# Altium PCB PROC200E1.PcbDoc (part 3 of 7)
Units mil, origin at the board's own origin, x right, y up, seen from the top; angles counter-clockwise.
Board outline 4163.97 x 3505.34 mil, 6 copper layers (Top Layer, GND1, SIG1, PWR, GND2, Bottom), stack 58.132 mil thick; 367 components, 387 nets, 1784 pads, 858 vias.
Unrouted connection lines stored in the file: 17.
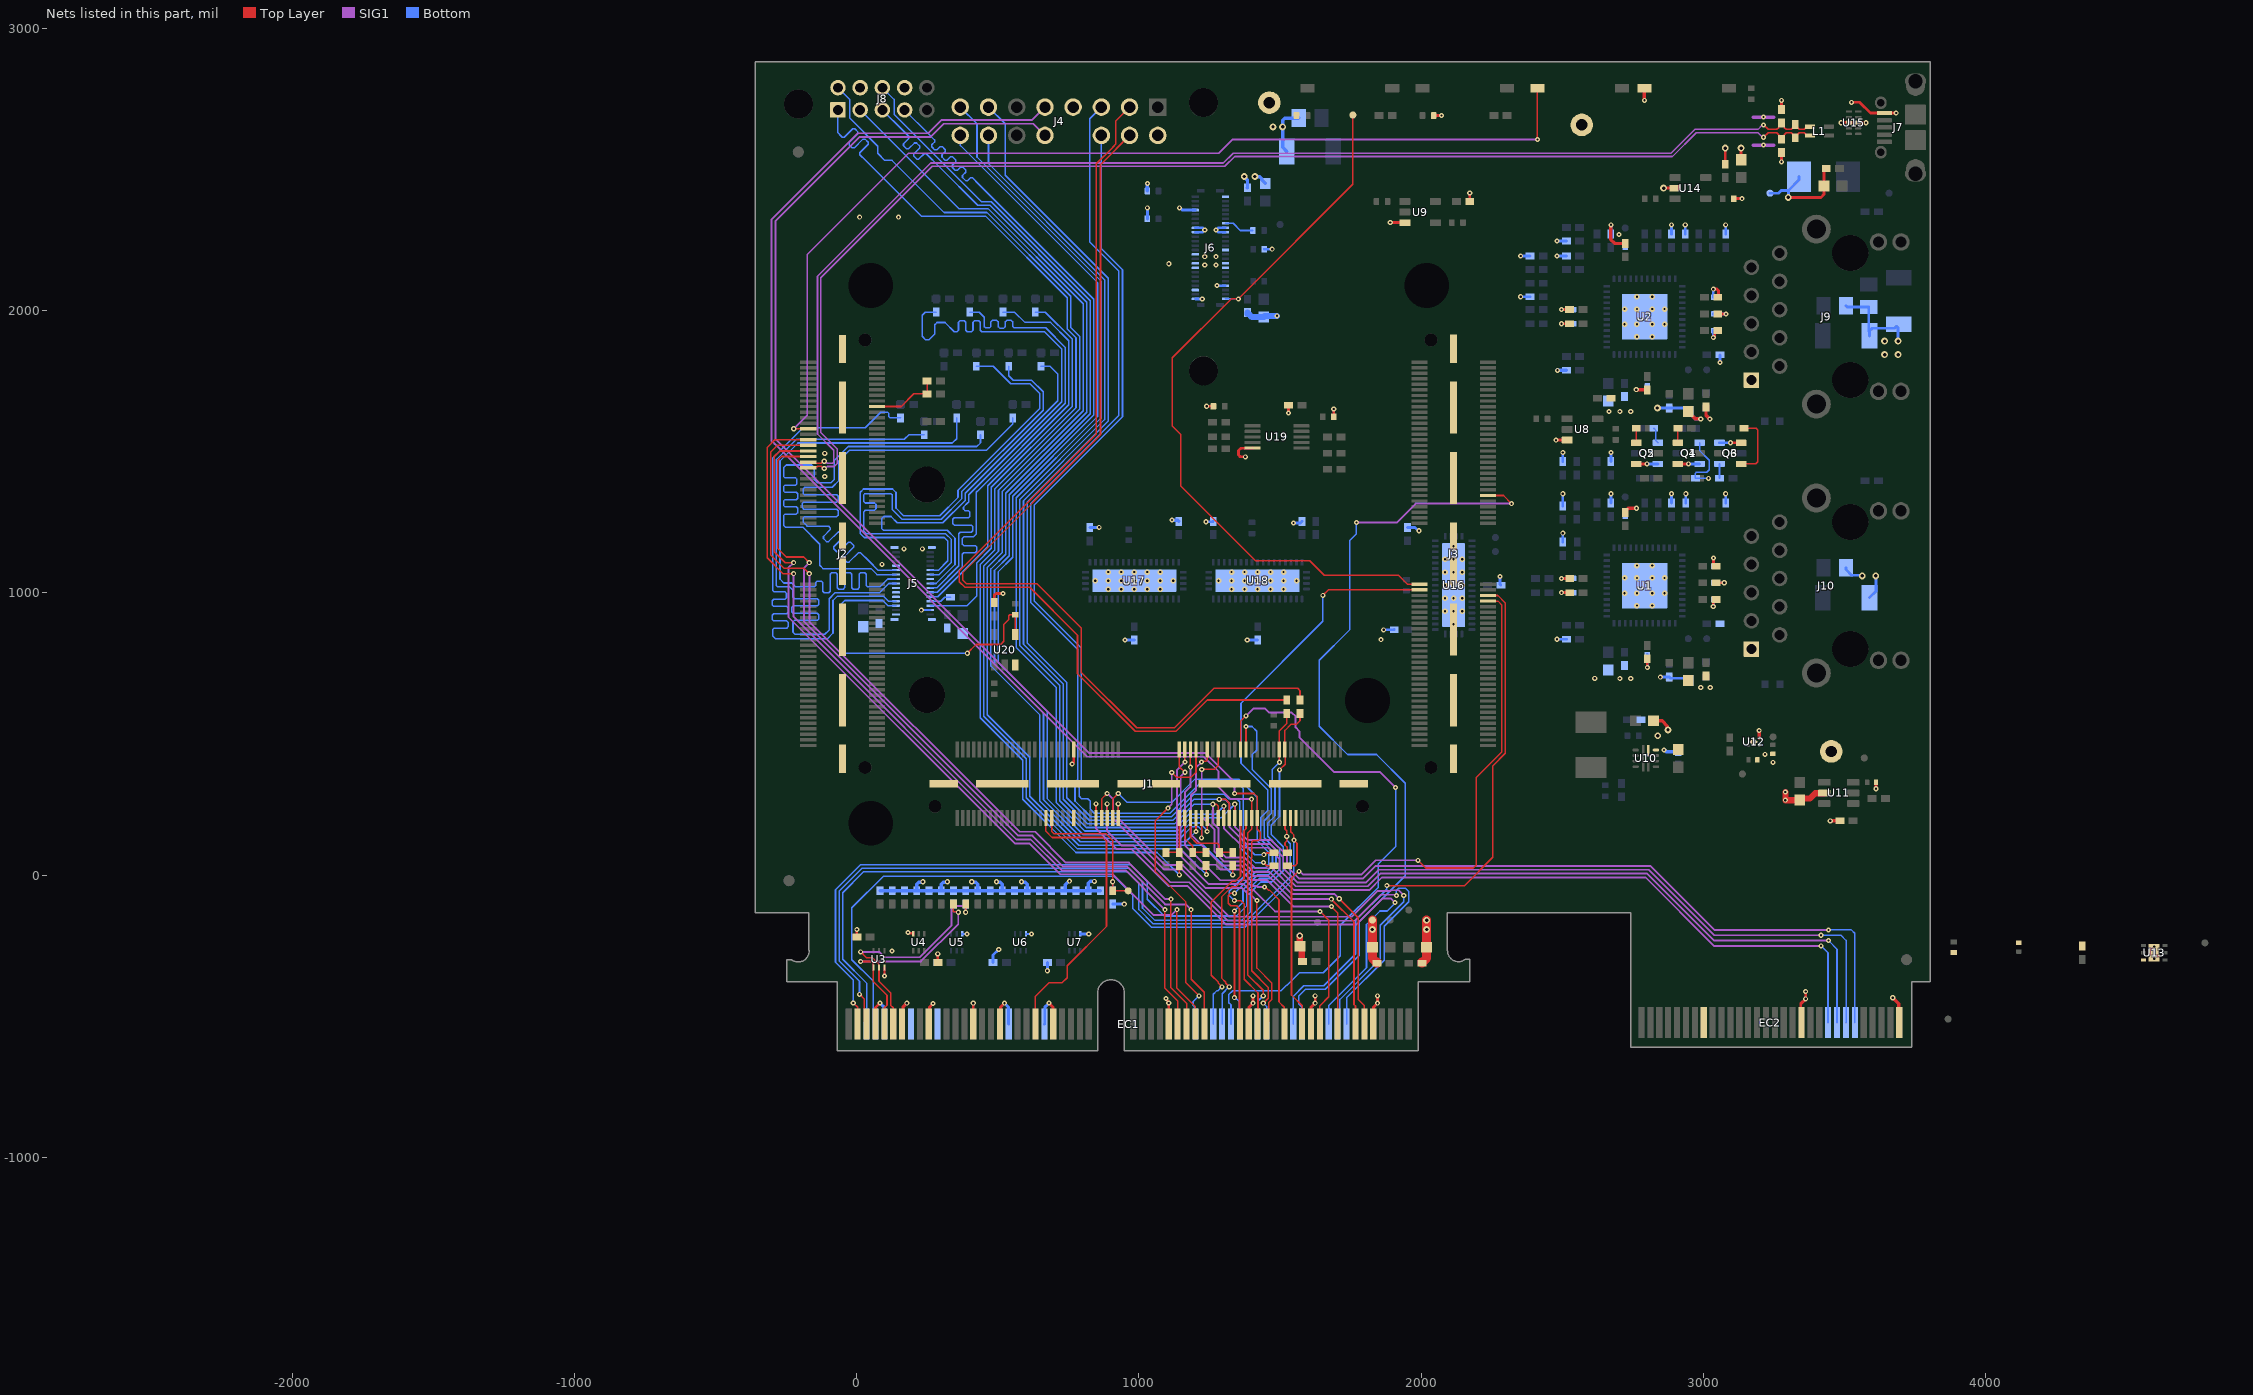
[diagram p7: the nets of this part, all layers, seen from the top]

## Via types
v1: diameter 18, hole 8, Top Layer to Bottom, tented both sides, 729 vias
v2: diameter 19.68, hole 7.87, Top Layer to Bottom, 77 vias
v3: diameter 24, hole 12, Top Layer to Bottom, tented both sides, 52 vias

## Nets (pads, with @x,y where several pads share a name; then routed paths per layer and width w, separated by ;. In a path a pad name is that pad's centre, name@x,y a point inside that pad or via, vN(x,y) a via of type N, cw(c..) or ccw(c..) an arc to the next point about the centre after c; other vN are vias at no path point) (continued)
AM26x_EQEP0_B: EC1.102 J1.69 | length 1926.2
  Top Layer w5.66: J1.69@847.97,201.89 v1(847.97,252.36)
  SIG1 w6.66: v1(847.97,252.36) 847.97,164.6 920.86,91.71 974.35,91.71 1105.1,-39.05 1172.37,-39.05 1308.99,-175.68 1770.43,-175.68 1862.69,-83.41 1893.44,-83.41 1907.51,-97.49 v1(1907.51,-97.56)
  Bottom w5.66: EC1.102@1672.7,-528.32 1672.7,-462.38 1806.39,-328.69 1806.39,-175.06 1854.07,-127.37 1880.23,-127.37 1907.51,-100.09 v1(1907.51,-97.56)
AM26x_EQEP0_INDEX: EC1.106 J1.65 | length 1973.5
  Top Layer w5.66: J1.65@887.34,201.89 v1(887.34,252.36)
  SIG1 w6.66: v1(887.34,252.36) 887.34,156.02 938,105.37 980.01,105.37 1110.76,-25.39 1178.02,-25.39 1314.65,-162.02 1764.77,-162.02 1857.03,-69.75 1899.1,-69.75 1899.18,-69.84 1910.14,-69.84 v1(1912.31,-72.01)
  Bottom w5.66: EC1.106@1735.69,-528.32 1735.69,-435.19 1869.38,-301.5 1869.38,-181.3 1956.3,-94.38 1956.3,-57.87 1945.86,-47.43 1919.06,-47.43 1912.31,-54.17 v1(1912.31,-72.01)
AM26x_EQEP0_STROBE: EC1.104 J1.67 | length 1967.2
  Top Layer w5.66: J1.67@867.66,201.89 867.66,269.68 v1(887.34,289.36)
  SIG1 w6.66: v1(887.34,289.36) 908.38,268.32 908.38,200.3 1089.5,19.19 1152.77,19.19 1319.53,-147.58 1754.04,-147.58 1845.53,-56.09 1891.39,-56.09 1893.8,-53.68 1919.98,-53.68 v1(1938.31,-72.01)
  Bottom w5.66: EC1.104@1704.2,-528.32 1712.19,-520.33 1712.19,-440.79 1855.38,-297.6 1855.38,-177.4 1938.31,-94.47 v1(1938.31,-72.01)
AM26x_FSIRX0_CLK: J1.55 R39.2 R40.2 | length 254
  Top Layer w5.66: J1.55@1182.62,201.89 1182.62,134.8 1204.46,112.96 1277.44,112.96 1285.23,105.17 R40.2@1285.23,80.5 R39.2@1332.54,80.5
AM26x_FSIRX0_DATA0: J1.59 R126.2 R127.2 | length 168.8
  Top Layer w5.66: R127.2@1096,80.5 R126.2@1143.25,80.5 ; J1.59@1143.25,201.89 R126.2@1143.25,80.55 ; R126.2@1143.25,80.5 R126.2@1143.25,80.55 ; R126.2@1143.25,80.5 R126.2@1143.31,80.5 R126.2@1143.25,80.55
AM26x_FSIRX0_DATA1: J1.57 R41.2 R125.2 | length 180.2
  Top Layer w5.66: J1.57@1162.93,201.89 1162.93,129.29 1190.61,101.61 R125.2@1190.61,80.5 R41.2@1237.92,80.5
AM26x_FSITX0_CLK: J1.49 J8.7 | length 3792.8
  Top Layer w5.66: v1(1241.67,154) J1.49@1241.67,201.89
  Bottom w5.66: J8.7@169.74,2711 255.8,2624.94 275.94,2604.8 275.94,2597.54 265.85,2587.45 265.85,2580.19 276.74,2569.31 284,2569.31 295.93,2581.24 303.19,2581.24 314.08,2570.36 314.08,2563.1 302.14,2551.16 302.14,2543.9 313.03,2533.02 320.29,2533.02 332.22,2544.95 339.48,2544.95 350.37,2534.07 350.37,2526.81 338.43,2514.87 338.43,2507.62 349.32,2496.73 356.57,2496.73 368.51,2508.66 375.77,2508.66 386.65,2497.78 386.65,2490.52 374.99,2478.85 374.99,2471.6 385.87,2460.71 393.13,2460.71 402.95,2470.53 410.21,2470.53 432.75,2447.99 840.4,2040.34 840.4,1629.73 553.06,1342.39 553.06,1126.09 500.92,1073.95 500.92,752.84 674.59,579.17 674.59,271.64 802.93,143.3 1141.52,143.3 1182.71,184.49 1214.93,184.49 1239.31,160.11 1239.31,156.36 v1(1241.67,154)
AM26x_FSITX0_DATA0: J1.53 J8.5 | length 3792.3
  Top Layer w5.66: v1(1202.3,154) J1.53@1202.3,201.89
  Bottom w5.66: J8.5@91,2711 164.5,2637.5 184.65,2617.35 184.65,2610.1 165.66,2591.11 165.66,2583.85 176.55,2572.97 183.81,2572.97 204.78,2593.94 212.03,2593.94 222.92,2583.05 222.92,2575.79 202.08,2554.96 202.08,2547.7 212.97,2536.81 220.23,2536.81 239.08,2555.66 246.34,2555.66 293,2509 429.02,2372.98 471.95,2372.98 815.08,2029.85 815.08,1640.22 527.74,1352.88 527.74,1136.58 475.6,1084.43 475.6,740.68 649.27,567.01 649.27,261.16 792.44,117.98 1166.28,117.98 v1(1202.3,154)
AM26x_FSITX0_DATA1: J1.51 J8.6 | length 3797.3
  Top Layer w5.66: v1(1221.99,132) J1.51@1221.99,201.89
  Bottom w5.66: J8.6@91,2789.74 132.55,2748.19 132.55,2695.59 442.5,2385.64 477.2,2385.64 827.74,2035.1 827.74,1634.98 540.4,1347.63 540.4,1131.33 488.26,1079.19 488.26,747.59 661.93,573.92 661.93,266.4 797.69,130.64 1146.76,130.64 1187.95,171.83 1209.69,171.83 1221.99,159.53 v1(1221.99,132)
AM26x_GPIO15: EC1.81 J3.57 | length 2180.3
  Top Layer w5.66: v1(1338.28,-64.45) 1324.8,-64.45 1316.31,-72.94 1316.31,-99.67 1325.7,-109.06 1346.32,-109.06 1356.34,-119.08 1356.34,-526.93 EC1.81@1357.74,-528.32 ; v1(1651.73,991) 1670.97,1010.24 J3.57@1993.48,1010.24
  Bottom w5.66: v1(1338.28,-64.45) 1416.03,13.3 1453.8,13.3 1473.09,32.6 1473.09,85.08 1431.5,126.68 1431.5,203.88 1456.54,228.92 1456.54,301.33 1361.64,396.24 1361.64,609.22 1651.73,899.31 v1(1651.73,991)
AM26x_GPIO81: EC1.96 J3.72 | length 2894.4
  Top Layer w5.66: J3.72@2236.48,1344.88 2291.59,1344.88 v1(2320.41,1316.07)
  SIG1 w6.66: v1(1770.7,1248.95) 1913.05,1248.95 1980.18,1316.07 v1@2321,1316.07
  Bottom w5.66: EC1.96@1578.21,-528.32 1577.81,-527.92 1577.81,-468.03 1566.27,-456.49 1566.27,-428.74 1590.16,-404.85 1660.15,-404.85 1781.07,-283.93 1781.07,-164.57 1943.57,-2.07 1943.57,325.34 1841.82,427.09 1739.25,427.09 1638.79,527.55 1638.79,761.04 1746.32,868.57 1746.32,1184.77 1770.7,1209.15 v1(1770.7,1248.95)
AM26x_I2C2_SCL: EC1.87 J1.61 | length 1181.2
  Top Layer w5.66: J1.61@926.71,201.89 v1(926.71,252.36) ; v1(1418.02,-90.45) 1418.02,-329.22 1470.85,-382.06 1470.85,-441.3 1460.22,-451.93 1460.22,-520.33 EC1.87@1452.23,-528.32
  SIG1 w6.66: v1(926.71,252.36) 926.71,201.29 1092.7,35.3 1155.97,35.3 1237.39,-46.12 1366.19,-46.12 1387.27,-67.2 1394.77,-67.2 v1(1418.02,-90.45)
AM26x_I2C2_SDA: EC1.85 J1.63 | length 1622.6
  Top Layer w5.66: J1.63@907.03,201.89 907.03,269.68 v1(926.71,289.36) ; v1(1338.12,-90.45) 1360.63,-90.45 1372.76,-102.58 1372.76,-368.85 1421.93,-418.02 1421.93,-527.13 EC1.85@1420.73,-528.32
  Bottom w5.66: v1(926.71,289.36) 957.91,258.17 1116.84,258.17 1198.77,340.1 1354.37,340.1 1418.84,275.63 1418.84,121.43 1446.47,93.8 1446.47,93.67 1460.43,79.71 1460.43,37.84 1448.56,25.96 1403.47,25.96 1320.45,-57.07 1320.45,-72.78 v1(1338.12,-90.45)
AM26x_LIN1_RXD: EC1.76 J1.37 | length 810.9
  Top Layer w5.66: v1(1293.91,-396.11) 1293.91,-395.79 1281.7,-383.58 1281.7,-379.58 1256.64,-354.52 1256.64,-95.18 1329.58,-22.24 1342.1,-22.24 1359.78,-4.56 J1.37@1359.78,201.89
  Bottom w5.66: EC1.76@1263.25,-528.32 1263.25,-422.44 1275.23,-410.46 1279.56,-410.46 v1(1293.91,-396.11)
AM26x_LIN1_TXD: EC1.78 J1.35 | length 797.6
  Top Layer w5.66: v1(1320.01,-396.11) 1320.01,-395.79 1307.81,-383.58 1307.81,-379.58 1292.82,-364.59 1292.82,-77.48 1328.29,-42 1344.02,-42 1372.44,-13.57 1372.44,156.89 1379.47,163.92 J1.35@1379.47,201.89
  Bottom w5.66: EC1.78@1294.75,-528.32 1294.75,-420.49 1319.12,-396.11 v1(1320.01,-396.11)
AM26x_MCAN0_RX: EC1.80 J1.38 | length 2056
  Top Layer w5.66: J1.38@1359.78,444.88 1360.14,445.24 1360.14,544.74 v1(1379.47,564.07)
  SIG1 w6.66: v1(1379.47,564.07) 1405.32,589.92 1446.92,589.92 1461.17,575.67 1541.31,575.67 1554.97,562.01 1554.97,523.03 1568.85,509.15 1568.85,487.71 1691.57,365 1854.45,365 v1(1909.29,310.15)
  Bottom w5.66: EC1.80@1326.24,-528.32 1326.24,-459.67 1318.64,-452.07 1318.64,-423.45 1332.54,-409.56 1503.62,-409.56 1522.24,-390.94 1523.67,-390.94 1568.57,-346.05 1653.05,-346.05 1713.66,-285.43 1713.66,-178.26 1847.27,-44.65 1847.27,38 1909.29,100.02 v1(1909.29,310.15)
AM26x_MCAN0_TX: EC1.82 J1.36 | length 1320.1
  Top Layer w5.66: v1(1338.12,-434.33) 1338.54,-433.91 v1@1338.54,-127.37 ; J1.36@1379.47,444.88 v1(1379.47,526.36)
  Bottom w5.66: v1(1338.12,-434.33) 1341.46,-434.33 1355.95,-448.83 1355.95,-526.54 EC1.82@1357.74,-528.32 ; v1(1338.12,-127.37) 1368.69,-96.8 1368.69,-51.95 1421.27,0.64 1459.04,0.64 1485.75,27.35 1485.75,90.33 1444.16,131.92 1444.16,192.74 1469.2,217.79 1469.2,306.58 1400.97,374.81 1400.97,426.15 1416.98,442.16 1416.98,510.02 1400.64,526.36 v1(1379.47,526.36)
AM26x_MCAN1_RX: EC1.94 J3.56 | length 2079.9
  Top Layer w5.66: v1(1878.5,-37.05) 1879.22,-37.76 2153.38,-37.76 2253.91,62.78 2253.91,386.75 2298.32,431.15 2298.32,964.08 2271.85,990.55 J3.56@2236.48,990.55
  Bottom w5.66: EC1.94@1546.72,-528.32 1546.72,-429.88 1584.41,-392.19 1654.91,-392.19 1768.41,-278.69 1768.41,-159.33 1877.89,-49.85 1877.89,-37.66 v1(1878.5,-37.05)
AM26x_MCAN1_TX: EC1.95 J3.54 | length 2252.1
  Top Layer w5.66: v1(1566.91,13.31) 1565.1,13.31 1540.54,-11.26 1540.54,-425.29 1578.21,-462.97 EC1.95@1578.21,-528.32 ; v1(1988.7,52.27) 2015.96,25.01 2184.8,25.01 2195,35.21 2195,345.74 2285.66,436.39 2285.66,957.06 2271.85,970.87 J3.54@2236.48,970.87
  SIG1 w6.66: v1(1566.91,13.31) 1569.98,13.31 1580.63,2.66 1789.53,2.66 1839.14,52.27 v1(1988.7,52.27)
AM26x_SDFM0_CLK0: EC1.72 J1.54 | length 1173.1
  Top Layer w5.66: v1(1102.58,237.09) v1(1102.58,237.09) 1058.45,192.88 1058.45,12.51 1166.44,-95.48 1166.44,-381.4 v1@1212.65,-427.61 ; v1(1116.3,363.64) 1133.36,346.58 1184.86,346.58 1202.3,364.02 J1.54@1202.3,444.88
  SIG1 w6.66: v1(1102.58,237.09) 1116.3,250.81 v1(1116.3,363.64)
  Bottom w5.66: EC1.72@1200.26,-528.32 1197.92,-525.98 1197.92,-468.03 1191.63,-461.75 1191.63,-449.11 v1(1212.89,-427.85)
AM26x_SDFM0_CLK3: EC1.109 J1.46 | length 1422.9
  Top Layer w5.66: v1(1222.62,374.35) 1222.68,374.42 1266.62,374.42 1280.6,388.4 1280.6,444.44 J1.46@1281.04,444.88 ; v1(1709.89,-83.88) 1776.97,-150.96 1776.97,-440.75 1798.68,-462.47 EC1.109@1798.68,-528.32
  SIG1 w6.66: v1(1222.62,374.35) 1222.62,206.11 1268,160.73 1268,83 1303.09,47.91 1368.75,47.91 1406.27,10.39 1463.57,10.39 1540.73,-66.78 1692.79,-66.78 v1(1709.89,-83.88)
AM26x_SDFM0_D0: EC1.91 J1.60 | length 1240.2
  Top Layer w5.66: J1.60@1143.25,444.88 1143.25,384.09 v1(1162.93,364.41) ; v1(1444.66,-42.51) 1447.9,-42.51 1458.65,-53.25 1462.65,-53.25 1496.38,-86.99 1496.38,-449.48 1514.93,-468.03 1514.93,-528.04 EC1.91@1515.22,-528.32
  SIG1 w6.66: v1(1162.93,364.41) 1148.29,349.77 1148.29,89.03 1214.65,22.67 1246.99,22.67 1288,-18.34 1377.04,-18.34 1397.21,-38.51 1417.4,-38.51 1421.4,-42.51 v1(1444.66,-42.51)
AM26x_SDFM0_D1: EC1.99 J1.58 | length 1395.6
  Top Layer w5.66: v1(1162.93,400.41) J1.58@1162.93,444.88 ; EC1.99@1641.2,-528.32 1641.2,-463.23 1672.94,-431.49 1672.94,-160.02 1642.17,-129.25 v1(1641.82,-129.25)
  SIG1 w6.66: v1(1162.93,400.41) 1134.63,372.11 1134.63,80.37 1247,-32 1371.39,-32 1392.93,-53.54 1407.03,-53.54 1482.62,-129.13 1641.7,-129.13 v1(1641.82,-129.25)
AM26x_SDFM0_D2: EC1.103 J1.56 | length 1381.5
  Top Layer w5.66: v1(1182.31,382.41) J1.56@1182.31,444.57 ; v1(1681.99,-111.78) 1681.99,-111.89 1704.2,-134.09 EC1.103@1704.2,-528.32
  SIG1 w6.66: v1(1182.31,382.41) 1182.31,312.59 1162.93,293.22 1162.93,106.21 1232.82,36.33 1272.42,36.33 1289.13,19.61 1358.41,19.61 1394.96,-16.93 1452.25,-16.93 1546.23,-110.92 1681.13,-110.92 v1(1681.99,-111.78)
AM26x_SDFM0_D3: EC1.107 J1.50 | length 1403.4
  Top Layer w5.66: v1(1221.77,400.34) 1224.13,402.7 1236.69,402.7 1241.84,407.85 1241.84,444.72 J1.50@1241.67,444.88 ; v1(1681.73,-85.33) 1761.98,-165.59 1761.98,-458.88 1767.19,-464.08 EC1.107@1767.19,-528.32
  SIG1 w6.66: v1(1221.77,400.34) 1202.87,381.44 1202.87,300.87 1183.97,281.97 1183.97,144.09 1294.79,33.28 1364.07,33.28 1400.61,-3.27 1457.91,-3.27 1539.96,-85.33 v1(1681.73,-85.33)
AM26x_SPI0_CLK: EC1.71 J2.34 | length 3005.1
  Top Layer w5.66: v1(-223.39,1107) -253.6,1107 -291.87,1145.27 -291.87,1483.82 -273.13,1502.56 J2.34@-171.52,1502.56 ; v1(1134.55,-122.64) 1134.55,-400.76 1199.01,-465.22 1199.01,-527.08 EC1.71@1200.26,-528.32
  SIG1 w6.66: v1(-223.39,1107) -241.72,1088.67 -241.72,914.32 560.26,112.35 611.21,112.35 720.7,2.86 906.77,2.86 1050.6,-140.97 1116.22,-140.97 v1(1134.55,-122.64)
AM26x_SPI0_CS0: EC1.73 J2.36 | length 2994.3
  Top Layer w5.66: J2.36@-171.52,1482.87 -266.32,1482.87 -279.21,1469.98 -279.21,1156.27 -250.02,1127.08 -188.08,1127.08 v1(-168,1107) ; v1(1184.91,-122.64) 1184.91,-368.86 1231.75,-415.7 EC1.73@1231.75,-528.32
  SIG1 w6.66: v1(-168,1107) -186.33,1088.67 -186.33,897.57 571.58,139.67 622.53,139.67 732.01,30.18 958.6,30.18 1092.59,-103.81 1166.08,-103.81 v1(1184.91,-122.64)
AM26x_SPI0_D0: EC1.69 J2.32 | length 2994.7
  Top Layer w5.66: J2.32@-171.52,1522.24 -281.06,1522.24 -304.53,1498.78 -304.53,1134.12 -258.08,1087.67 -187.67,1087.67 v1(-168,1068) ; v1@1112,-85.48 1112.53,-86.01 1112.53,-398.36 1168.76,-454.6 EC1.69@1168.76,-528.32
  SIG1 w6.66: v1(-168,1068) -167.4,1067.4 -167.4,897.96 577.23,153.33 631.96,153.33 741.44,43.84 964.26,43.84 1093.58,-85.48 v1@1112,-85.48
  other v1: 1113.33,-85.48
AM26x_SPI0_D1: EC1.67 J2.30 | length 2987
  Top Layer w5.66: v1(-223.39,1068) -261,1068 -317.19,1124.19 -317.19,1514.7 -289.96,1541.93 J2.30@-171.52,1541.93 ; v1(1092.1,-122.64) 1092.1,-400.86 1137.27,-446.02 EC1.67@1137.27,-528.32
  SIG1 w6.66: v1(-223.39,1068) -223.39,915.31 565.92,126.01 616.87,126.01 726.36,16.52 952.94,16.52 v1(1092.1,-122.64)
AM26x_SPI3_CLK: EC2.168 J1.41 J4.13 | length 6327.2
  Top Layer w5.66: v1(1284.57,268.3) v1(1284.57,268.3) 1306.58,268.39 1320.41,254.55 J1.41@1320.41,201.89
  SIG1 w6.66: v1(1284.57,268.3) 1305.77,268.3 1320.33,253.74 1320.33,170.35 1380.23,110.45 1463.54,110.45 1511.17,62.82 1511.17,23.81 1560.78,-25.8 1805.17,-25.8 1849.61,18.64 2806.47,18.64 3038.38,-213.27 v1(3416.74,-213.27)
  Bottom w5.66: J4.13@466.91,2720.91 526.17,2661.65 526.17,2479.86 891.04,2114.99 891.04,1608.76 603.7,1321.41 603.7,822.98 744.41,682.27 744.41,273.44 823.91,193.94 1120.54,193.94 1195.4,268.8 1284.07,268.8 v1(1284.57,268.3) ; v1(3416.74,-213.27) 3487.27,-213.27 3505.54,-231.54 3505.54,-522.47 EC2.168@3505.04,-522.97
AM26x_SPI3_CS0: EC2.170 J1.39 J4.16 | length 6316.5
  Top Layer w5.66: v1(1339.54,251.35) 1339.82,251.07 1339.82,202.17 J1.39@1340.1,201.89
  SIG1 w6.66: v1(1339.54,251.35) 1340.52,250.37 1340.52,169.48 1385.89,124.11 1469.28,124.11 1524.83,68.56 1524.83,43.26 1524.83,29.47 1566.44,-12.14 1794.05,-12.14 1838.49,32.3 2812.2,32.3 3038.97,-194.47 v1(3443.05,-194.47)
  Bottom w5.66: J4.16@366.91,2620.91 367.48,2620.34 367.48,2584.83 853.06,2099.26 853.06,1624.49 565.72,1337.15 565.72,806.47 706.43,665.77 706.43,257.71 808.18,155.96 1136.27,155.96 1182.79,202.48 1290.66,202.48 v1(1339.54,251.35) ; v1(3443.05,-194.47) 3524.47,-194.47 3536.54,-206.54 EC2.170@3536.54,-522.97
AM26x_SPI3_D0: EC2.164 J1.45 J4.14 | length 6125.8
  Top Layer w5.66: v1(1261.97,250.97) 1262.14,250.8 1275.21,250.8 1281.04,244.97 J1.45@1281.04,201.89
  SIG1 w6.66: v1(1261.97,250.97) 1261.97,186.08 1281.82,166.23 1281.82,88.5 1308.75,61.57 1374.41,61.57 1411.93,24.05 1472.3,24.05 1549.46,-53.12 1816.49,-53.12 1860.93,-8.68 2795.16,-8.68 3037.35,-250.87 v1(3416.74,-250.87)
  Bottom w5.66: J4.14@466.91,2620.91 466.91,2521.22 878.38,2109.75 878.38,1614 591.04,1326.66 591.04,817.74 731.75,677.03 731.75,268.2 818.66,181.28 1125.78,181.28 1195.48,250.97 v1(1261.97,250.97) ; v1(3416.74,-250.87) 3441.39,-275.52 3441.39,-522.32 EC2.164@3442.05,-522.97
AM26x_SPI3_D1: EC2.166 J1.43 J4.15 | length 6284.5
  Top Layer w5.66: J1.43@1300.73,201.89 1300.83,201.99 1300.83,244.03 v1(1300.93,244.13)
  SIG1 w6.66: v1(1300.93,244.13) 1300.93,166.44 1370.77,96.6 1458.08,96.6 1497.51,57.16 1497.51,18.15 1555.12,-39.46 1810.83,-39.46 1855.27,4.98 2800.81,4.98 3037.86,-232.07 v1(3443.05,-232.07)
  Bottom w5.66: J4.15@366.91,2720.91 426.17,2661.65 426.17,2544.05 865.72,2104.5 865.72,1619.24 578.38,1331.9 578.38,812.49 719.09,671.78 719.09,262.95 813.42,168.62 1131.03,168.62 1177.54,215.14 1271.94,215.14 v1(1300.93,244.13) ; v1(3443.05,-232.07) 3473.54,-262.57 EC2.166@3473.54,-522.97
AM26x_UART0_RXD: EC1.86 J1.33 J4.9 | length 5010.5
  Top Layer w5.66: v1(1399.09,268.81) 1399.15,268.74 J1.33@1399.15,201.89 1399.15,162.06 1386,148.9 1386,64.93 1385.19,64.12 1385.19,17.88 1386,17.07 1386,-354 1440.36,-408.36 v1(1440.36,-427.85)
  SIG1 w6.66: J4.9@666.91,2720.91 621.8,2675.81 301.65,2675.81 254.23,2628.39 20.9,2628.39 3.89,2628.39 -290.98,2333.52 -301.32,2323.18 -301.32,1538 -290.98,1527.66 817.32,419.36 1229.8,419.36 1282.24,366.92 1282.24,311.81 1323.97,270.08 1397.82,270.08 v1(1399.09,268.81)
  Bottom w5.66: EC1.86@1420.73,-528.32 1422.53,-526.52 1422.53,-445.68 v1(1440.36,-427.85)
AM26x_UART0_TXD: EC1.88 J1.31 J4.10 | length 5014.6
  Top Layer w5.66: v1(1339.09,289.15) 1407.94,289.15 1418.92,278.17 1418.92,201.97 J1.31@1418.84,201.89 1418.84,162.47 1429.88,151.42 1429.88,129.88 1422.26,122.26 1404.67,122.26 1399.45,117.05 1399.45,60.48 1397.85,58.87 1397.85,23.13 1399.45,21.52 1399.45,-339.32 1458.19,-398.06 1458.19,-436.05 v1(1440.36,-453.88)
  SIG1 w6.66: J4.10@666.91,2620.91 625.67,2662.15 308.41,2662.15 261,2614.73 9.55,2614.73 -287.66,2317.52 -287.66,1543.66 822.98,433.02 1235.46,433.02 1339.09,329.38 v1(1339.09,289.15)
  Bottom w5.66: v1(1440.36,-453.88) 1452.23,-465.77 EC1.88@1452.23,-528.32
AM26x_USB0_DM: J2.40 L1.3 R92.1 R93.1 | length 4575.4
  Top Layer w5: J2.40@-171.52,1443.5 -168.01,1447.01 -139.27,1447.01 -138.54,1447.74 -125.91,1447.74 -118.52,1440.35 v1(-115,1440.35) ; v1(3212.89,2614.22) 3229.11,2630.44 3260.57,2630.44 3267.5,2623.51 3267.5,2616.37 R93.1@3276.81,2607.05 3286.12,2616.37 3286.12,2623.51 3293.05,2630.44 3311.74,2630.44 R92.1@3325.81,2616.37 ; R92.1@3325.81,2612.43 R92.1@3325.81,2616.37 ; L1.3@3377.54,2620.31 3367.69,2620.31 3357.55,2630.44 3339.89,2630.44 R92.1@3325.81,2616.37
  SIG1 w5.7: v1(-115,1440.35) -111.67,1440.35 -104.52,1447.5 -79.64,1447.5 -69.26,1457.88 -69.26,1509.85 -127.18,1567.77 -127.18,2116.65 267.28,2511.1 1303.95,2511.1 1339.02,2546.17 2890.17,2546.17 2974.21,2630.2 3193.57,2630.2 3207.2,2616.57 3210.53,2616.57 v1(3212.89,2614.22)
AM26x_USB0_DP: J2.38 L1.2 R90.1 R92.2 | length 4575.4
  Top Layer w5: J2.38@-171.52,1463.19 -168.01,1459.69 -139.27,1459.69 -138.54,1458.96 -125.91,1458.96 -118.52,1466.35 v1(-115,1466.35) ; v1(3212.89,2657.89) 3229.11,2641.66 3260.57,2641.66 3267.5,2648.59 3267.5,2655.74 R90.1@3276.81,2665.05 3286.12,2655.74 3286.12,2648.59 3293.05,2641.66 3311.74,2641.66 R92.2@3325.81,2655.74 ; R92.2@3325.81,2659.68 R92.2@3325.81,2655.74 ; L1.2@3377.54,2651.8 3367.69,2651.8 3357.55,2641.66 3339.89,2641.66 R92.2@3325.81,2655.74
  SIG1 w5.7: v1(-115,1466.35) -111.67,1466.35 -104.52,1459.2 -84.49,1459.2 -80.96,1462.72 -80.96,1505 -138.88,1562.92 -138.88,2121.49 262.43,2522.8 1299.11,2522.8 1334.17,2557.87 2885.32,2557.87 2969.36,2641.9 3193.57,2641.9 3207.2,2655.54 3210.53,2655.54 v1(3212.89,2657.89)
AM26x_USB0_DRVVBUS: J2.26 SW1.1 | length 3626.7
  Top Layer w5.66: v1(-222.99,1581.3) J2.26@-171.52,1581.3 ; SW1.1@2411.74,2788 2412,2787.74 v1(2412,2606)
  SIG1 w6.66: v1(-222.99,1581.3) -175.06,1629.23 -175.06,2198.8 183.54,2557.4 1282.54,2557.4 1331.14,2606 v1(2412,2606)
AM26x_VREFHI1: J1.85 R154.2 R155.1 TP18.1 | length 526.6
  Top Layer w5.66: J1.85@690.49,201.89 690.49,154.76 699.19,146.06 883.66,146.06 907.02,122.69 v1(907.02,-23.76) R154.2@907.02,-55.76 TP18.1@962,-55.76
  Bottom w5.66: 907.02,-40.01 v1(907.02,-23.76)
AM26x_VREFLO: EC1.43 J1.87 | length 1054.9
  Top Layer w5.66: EC1.43@633.33,-528.32 633.33,-429.67 682,-381 728,-381 745.54,-363.46 745.54,-321.55 885.13,-181.96 885.13,118.85 870.83,133.15 692.31,133.15 670.51,154.95 670.51,201.18 J1.87@671.01,201.69
BRD_CONN_DET: J6.36 R80.2 | length 107.8
  Bottom w5.66: J6.36@1306.63,2309.14 1333.86,2309.14 1359.09,2283.91 R80.2@1403.93,2283.91
CONN_MDIO0_MDC: J2.17 R159.2 R160.2 | length 242.8
  Top Layer w5.66: J2.17@71.48,1660.04 157.43,1660.04 202.53,1705.14 248.94,1705.14 R159.2@249.43,1704.65 R160.2@249.43,1750.66
CONN_OSPI1_CLK: J5.10 R24.2 | length 1401.8
  Bottom w5.66: J5.10@260.49,985.92 287.57,985.92 464.44,1162.79 464.44,1379.1 751.78,1666.44 751.78,1893.11 686.89,1958 596,1958 559.5,1994.5 R24.2@518.51,1994.5
CONN_OSPI1_CSn0: J5.7 R49.2 | length 2028
  Bottom w5.66: J5.7@139.23,970.18 112.83,970.18 95.8,987.2 -69.48,987.2 -84,972.68 -84,857.31 -104.68,836.63 -287.03,836.63 -291.6,841.2 -297.49,847.09 -297.49,869.69 -292.36,874.82 -248.21,874.82 -243.08,879.95 -243.08,895.35 -248.21,900.48 -293.74,900.48 -298.87,905.61 -298.87,921.01 -293.74,926.14 -248.21,926.14 -243.08,931.27 -243.08,946.67 -248.21,951.8 -293.74,951.8 -298.87,956.93 -298.87,972.33 -293.74,977.46 -253.82,977.46 -248.69,982.59 -248.69,997.99 -253.82,1003.12 -292.36,1003.12 -297.49,1008.25 -297.49,1039.84 -297.49,1477.64 -189.97,1585.16 30.16,1585.16 85,1640 109.46,1640 114.09,1635.37 114.09,1624.06 118.14,1620.01 R49.2@155.05,1620.01
CONN_OSPI1_CSn1: J5.8 R31.1 | length 78.3
  Bottom w5.66: J5.8@260.49,970.18 297.65,970.18 311.65,984.18 R31.1@333.03,984.18
CONN_OSPI1_D0: J5.14 R26.2 | length 2066.8
  Bottom w5.66: J5.14@260.49,1017.42 283.25,1017.42 361.42,1095.58 361.42,1180.76 361.42,1209.25 366.55,1214.38 405.76,1214.38 410.89,1219.51 410.89,1234.91 405.76,1240.04 345.56,1240.04 340.43,1245.17 340.43,1260.57 345.56,1265.7 395.92,1265.7 401.05,1270.83 401.05,1286.23 395.92,1291.36 383.61,1291.36 378.48,1296.49 378.48,1303.75 393.66,1318.94 396.95,1322.22 396.95,1347.41 726.46,1676.93 726.46,1863.9 665.08,1925.29 471.2,1925.29 442.71,1925.29 437.58,1930.42 437.58,1958.69 432.45,1963.82 417.05,1963.82 411.92,1958.69 411.92,1929.96 406.79,1924.83 391.39,1924.83 386.26,1929.96 386.26,1958.69 381.13,1963.82 365.73,1963.82 360.6,1958.69 360.6,1930.42 355.47,1925.29 349.49,1925.29 345.42,1925.29 312.98,1957.72 284.59,1957.72 276.67,1949.81 276.67,1917.36 256.31,1897 244,1897 232.13,1908.87 232.13,1983.37 243.26,1994.5 R26.2@281.66,1994.5
CONN_OSPI1_D1: J5.15 R28.2 | length 2078.7
  Bottom w5.66: J5.15@139.23,1033.17 113.79,1033.17 80.49,999.86 -77.14,999.86 -97.74,979.26 -97.74,868.63 -112.73,853.64 -218.61,853.64 -225.6,860.63 -225.6,868.67 -225.6,897.16 -220.47,902.29 -139.43,902.29 -134.3,907.42 -134.3,922.82 -139.43,927.95 -225.28,927.95 -230.42,933.08 -230.42,948.48 -225.28,953.61 -139.43,953.61 -134.3,958.74 -134.3,974.14 -139.43,979.27 -220.47,979.27 -225.6,984.4 -225.6,1005 -225.6,1008.98 -237.67,1021.05 -279.7,1021.05 -284.38,1025.73 -284.38,1472.54 -213.23,1543.7 168.73,1543.7 185.04,1560.01 R28.2@239.54,1560.01
CONN_OSPI1_D2: J5.16 R30.2 | length 1513.7
  Bottom w5.66: J5.16@260.49,1033.17 281.1,1033.17 348.31,1100.38 348.31,1193.91 320.57,1221.66 94.74,1221.66 88.11,1228.28 88.11,1262.33 96.19,1270.4 121.62,1270.4 143.9,1248.12 304.95,1248.12 384.29,1327.46 384.29,1352.66 712.38,1680.75 712.38,1775.11 684.66,1802.83 R30.2@653,1802.83
CONN_OSPI1_D3: J5.17 R33.2 | length 1952.4
  Bottom w5.66: J5.17@139.23,1048.92 109.92,1048.92 82,1021 67.75,1021 39.26,1021 34.13,1026.13 34.13,1065.87 29,1071 13.6,1071 8.47,1065.87 8.47,1017.65 3.34,1012.52 -12.06,1012.52 -17.19,1017.65 -17.19,1065.87 -22.32,1071 -37.72,1071 -42.85,1065.87 -42.85,1017.65 -47.98,1012.52 -63.38,1012.52 -68.51,1017.65 -68.51,1065.87 -73.64,1071 -89.04,1071 -94.17,1065.87 -94.17,1005.87 -99.3,1000.74 -114.7,1000.74 -119.83,1005.87 -119.83,1036.53 -124.96,1041.66 -140.36,1041.66 -145.49,1036.53 -145.49,1026.13 -150.62,1021 -198,1021 -216,1021 -230,1035 -258,1035 -271.72,1048.72 -271.72,1467.3 -207.98,1531.04 338.8,1531.04 354.02,1546.26 R33.2@354.02,1620.01
CONN_OSPI1_D4: J5.19 R35.2 | length 1854.2
  Bottom w5.66: J5.19@139.23,1064.66 72.05,1064.66 50.69,1086.02 -119.61,1086.02 -130.88,1097.29 -130.88,1172.37 -191.51,1232.99 -252.8,1232.99 -259,1239.19 -259,1245.3 -259,1273.79 -253.87,1278.92 -214.47,1278.92 -209.34,1284.05 -209.34,1299.45 -214.47,1304.58 -253.93,1304.58 -259.06,1309.71 -259.06,1325.11 -253.93,1330.24 -214.47,1330.24 -209.34,1335.37 -209.34,1350.77 -214.47,1355.9 -253.93,1355.9 -259.06,1361.03 -259.06,1376.43 -253.93,1381.56 -216.92,1381.56 -211.79,1386.69 -211.79,1402.09 -216.92,1407.22 -253.87,1407.22 -259,1412.35 -259,1436.16 -259,1443.5 -249.56,1452.95 -158.69,1452.95 -150,1444.25 -150,1402.76 -137.57,1390.33 -90.71,1390.33 -79,1402.04 -79,1469.35 -29.98,1518.38 425.62,1518.38 438.51,1531.27 R35.2@438.51,1560.01
CONN_OSPI1_D5: J5.20 R37.2 | length 1822.3
  Bottom w5.66: J5.20@260.49,1064.66 292.29,1064.66 335.65,1108.03 335.65,1188.67 315.66,1208.66 35.87,1208.66 25.63,1218.89 25.63,1259 25.63,1287.49 30.77,1292.62 63.2,1292.62 68.33,1297.75 68.33,1313.15 63.2,1318.28 30.77,1318.28 25.63,1323.41 25.63,1336.22 25.63,1348.14 28.95,1351.45 121.63,1351.45 126,1347.09 126,1295.62 160.83,1260.78 299.7,1260.78 371.63,1332.71 371.63,1357.9 660.66,1646.94 660.66,1712.15 619.44,1753.36 554.54,1753.36 538.51,1769.39 R37.2@538.51,1802.83
CONN_OSPI1_D6: J5.21 R45.2 | length 2191.3
  Bottom w5.66: J5.21@139.23,1080.41 75.59,1080.41 44.5,1111.5 13.63,1142.37 6.38,1142.37 -27.01,1108.98 -34.27,1108.98 -45.16,1119.87 -45.16,1127.12 -11.03,1161.25 -11.03,1168.5 -21.92,1179.39 -29.18,1179.39 -63.3,1145.27 -70.56,1145.27 -81.44,1156.16 -81.44,1163.41 -47.32,1197.54 -47.32,1204.79 -58.21,1215.68 -65.47,1215.68 -99.59,1181.56 -106.85,1181.56 -117.73,1192.44 -117.73,1199.7 -94.21,1223.22 -94.21,1230.48 -99.34,1235.61 -122.12,1235.61 -174.81,1235.61 -180.91,1241.72 -190,1250.8 -190,1265.08 -184.87,1270.21 -70.29,1270.21 -65.16,1275.34 -65.16,1290.74 -70.29,1295.87 -187.21,1295.87 -192.34,1301 -192.34,1316.4 -187.21,1321.53 -70.29,1321.53 -65.16,1326.66 -65.16,1342.06 -70.29,1347.19 -184.87,1347.19 -190,1352.32 -190,1358.56 -190,1368.18 -183.95,1374.23 -86.77,1374.23 -63,1398 -63,1467.45 -24.73,1505.72 460.69,1505.72 553,1598.02 R45.2@553,1620.01
CONN_OSPI1_D7: J5.22 R47.2 | length 1815.7
  Bottom w5.66: J5.22@260.49,1080.41 290.14,1080.41 322.99,1113.27 322.99,1183.43 310.42,1196 26.4,1196 12.57,1209.82 12.57,1356.15 24.15,1367.73 127.14,1367.73 139.17,1355.71 139.17,1300.35 166.08,1273.44 294.46,1273.44 358.97,1337.95 358.97,1363.14 648,1652.18 648,1706.9 614.2,1740.7 546.08,1740.7 483.95,1802.83 R47.2@424.02,1802.83
CONN_OSPI1_DQS: J5.12 R51.2 | length 1684.2
  Bottom w5.66: J5.12@260.49,1001.67 285.41,1001.67 374.08,1090.34 374.08,1108.15 374.08,1136.64 379.21,1141.77 420.38,1141.77 425.51,1146.9 425.51,1162.3 420.38,1167.43 379.21,1167.43 374.08,1172.56 374.08,1192.42 374.08,1192.66 380.33,1198.91 413.83,1198.91 423.55,1208.63 423.55,1268.33 423.55,1356.11 433.06,1365.63 739.12,1671.68 739.12,1869.15 669.44,1938.83 603,1938.83 557.58,1938.83 552.45,1943.96 552.45,1960.03 547.31,1965.17 531.92,1965.17 526.79,1960.03 526.79,1943.08 521.65,1937.95 506.26,1937.95 501.13,1943.08 501.13,1960.03 495.99,1965.17 480.6,1965.17 475.47,1960.03 475.47,1943.96 470.33,1938.83 467.5,1938.83 456.69,1938.83 452.27,1943.24 452.27,1976.3 434.07,1994.5 R51.2@400.09,1994.5
CONN_OSPI1_ECC_FAIL: J5.6 R53.2 | length 1400.1
  Bottom w5.66: J5.6@260.49,954.43 390.57,954.43 424.96,988.82 424.96,1105.41 477.1,1157.55 477.1,1373.85 764.44,1661.2 764.44,1898.36 668.29,1994.5 R53.2@633,1994.5
CONN_OSPI1_RESET_OUT0: J5.5 R123.2 U20.4 | length 1167.1
  Top Layer w5.66: v1(392,786) 423,817 510,817 521,828 521,888 538.83,905.83 538.83,918.93 542.15,922.25 R123.2@562.29,922.25 U20.4@562.29,852.66
  Bottom w5.66: J5.5@139.23,954.43 110.73,954.43 107.64,957.52 107.58,957.52 92.38,972.72 -42.02,972.72 -56.42,958.32 -56.42,789.32 -53.1,786 v1(392,786)
DAC_TCK: EC1.5 J1.22 R158.2 | length 2990.9
  Top Layer w5.66: v1(10.01,-422.63) 10.6,-422.63 26.91,-438.94 26.91,-520.33 EC1.5@34.9,-528.32 ; v1@1499.78,372.96 1499.78,374.74 1518.13,393.09 1518.13,444.01 J1.22@1517.26,444.88 1517.26,512.27 1539.99,535 1559.41,535 1570.71,546.3 R158.2@1570.71,573.04
  Bottom w5.66: v1(10.01,-422.63) 10.01,-375.99 -62.32,-303.66 -62.32,-56.97 19.16,24.51 964.84,24.51 1012.65,-23.3 1012.65,-116.85 1055.35,-159.54 1365.57,-159.54 1394.01,-131.11 1394.01,-62.43 1431.76,-24.68 1470.78,-24.68 1511.1,15.65 1511.1,100.79 1469.48,142.41 1469.48,178.67 1498.12,207.3 v1(1498.12,372.96)
DAC_TDI: EC1.8 J1.19 R156.2 | length 2579.2
  Top Layer w5.66: R156.2@1525.87,33.46 1553.64,33.46 1560,39.82 1560,112.5 1549.19,123.31 v1(1549.19,123.72) 1549.19,142.02 1537.49,153.72 1537.49,201.35 J1.19@1536.95,201.89
  Bottom w5.66: EC1.8@66.4,-528.32 58.4,-520.33 58.4,-375.73 -17.45,-299.88 -17.45,-116 94.83,-3.72 912.21,-3.72 978.53,-70.05 978.53,-118.53 1044.86,-184.86 1376.06,-184.86 1549.08,-11.84 1549.08,123.62 v1(1549.19,123.72)
DAC_TDO: EC1.6 J1.21 R157.2 | length 2598.2
  Top Layer w5.66: J1.21@1517.26,201.89 1517.63,201.52 1517.63,162.59 1523.63,156.59 v1(1523.63,137.21) 1523.24,136.82 1523.24,119.72 1517.63,114.11 1517.63,106.56 1525.87,98.33 R157.2@1525.87,78.82
  Bottom w5.66: EC1.6@34.9,-528.32 34.9,-382.8 -49.66,-298.24 -49.66,-62.21 24.4,11.85 959.6,11.85 999.99,-28.55 999.99,-57.51 999.99,-122.09 1050.1,-172.2 1370.81,-172.2 1536.42,-6.59 1536.42,111.27 1523.77,123.93 1523.77,137.08 v1(1523.63,137.21)
DAC_TMS: EC1.3 J1.24 R161.2 | length 2936.2
  Top Layer w5.66: v1(-12.34,-453) 3.41,-468.75 EC1.3@3.41,-528.32 ; v1(1498.12,399.61) 1497.85,399.88 1497.85,444.61 J1.24@1497.58,444.88 1497.58,510.49 1524.04,536.95 R161.2@1524.04,573.04
  Bottom w5.66: v1(-12.34,-453) -12.34,-371.55 -74.98,-308.91 -74.98,-51.73 13.92,37.17 970.09,37.17 1029.77,-22.51 1029.77,-85.52 1089.44,-145.2 1345.51,-145.2 1381.35,-109.36 1381.35,-57.19 1426.52,-12.02 1465.53,-12.02 1498.44,20.89 1498.44,95.54 1456.82,137.17 1456.82,184.3 1482,209.48 1482,320.46 1473.07,329.39 1473.07,374.56 v1(1498.12,399.61)
ETH1_LED0: Q1.1 R109.2 | length 51.1
  Top Layer w5.66: Q1.1@2909.66,1531.71 R109.2@2909.66,1582.81
ETH1_LED1: Q2.1 R111.2 | length 51.1
  Top Layer w5.66: Q2.1@2762.22,1531.71 R111.2@2762.22,1582.81
ETH1_LED2: Q3.1 R113.2 | length 226.4
  Top Layer w5.66: Q3.1@3133.87,1456.91 3185.91,1456.91 3193,1464 3193,1577 3187.19,1582.81 R113.2@3144.11,1582.81
ETH2_LED0: Q4.1 R116.2 | length 228.9
  Bottom w5.66: Q4.1@2986.43,1531.71 2986.43,1504.57 3021,1470 3021,1436.44 3012.02,1427.46 2974.98,1427.46 2971.67,1424.15 R116.2@2971.67,1405.81 v1(3018.18,1405.81)
ETH2_LED1: Q5.1 R119.2 | length 57.2
  Bottom w5.66: R119.2@2824.22,1582.81 2831.73,1575.31 2831.73,1538.97 Q5.1@2838.99,1531.71
ETH2_LED2: Q6.1 R120.2 | length 51.1
  Bottom w5.66: R120.2@3057.1,1405.81 Q6.1@3057.1,1456.91
EXT_VMON2: J3.59 J6.2 TP11.1 | length 2642.2
  Top Layer w5.66: TP11.1@1758,2693 1758,2447.27 v1(1352.15,2041.43) 1326.89,2041.43 1117.96,1832.49 1117.96,1590.99 1148.33,1560.62 1148.33,1378.24 1413.04,1113.52 1605.26,1113.52 1656.76,1062.03 1919.42,1062.03 1951.52,1029.92 J3.59@1993.48,1029.92
  Bottom w5.66: J6.2@1306.63,2041.43 v1(1352.15,2041.43)
GND: C1.1 C2.2 C3.2 C4.2 C5.2 C6.2 C7.2 C8.2 C9.1 C10.2 C11.2 C12.2 C13.2 C14.2 C15.1 C16.2 C17.2 C18.2 C19.2 C20.2 C21.1 C22.2 C23.1 C24.2 C25.1 C26.2 C27.1 C28.2 C29.1 C30.2 C31.1 C32.2 C33.2 C34.2 C35.2 C36.2 C37.1 C38.2 C39.2 C40.2 C41.2 C42.2 C43.2 C44.2 C45.1 C46.2 C47.2 C48.2 C49.2 C50.2 C51.1 C52.2 C53.2 C54.2 C55.2 C56.2 C57.1 C58.2 C59.1 C60.2 C61.1 C62.1 C63.1 C64.1 C65.1 C66.1 C67.1 C68.1 C69.1 C70.1 C71.1 C72.1 C73.1 C74.1 C75.2 C76.2 C77.2 C78.2 C79.1 C80.1 C81.1 C82.1 C83.1 C84.1 C85.1 C86.1 C87.1 C88.2 C89.1 C94.1 C97.2 C100.2 C102.1 C103.2 C104.1 C105.1 C108.1 C109.2 C110.2 C111.2 C112.2 C113.2 C114.2 C115.2 C116.2 C117.2 C118.2 C119.1 C120.1 C121.1 D1.1 EC1.7 EC1.10 EC1.13 EC1.16 EC1.19 EC1.22 EC1.29 EC1.35 EC1.38 EC1.46 EC1.47 EC1.65 EC1.83 EC1.97 EC1.111 EC2.135 EC2.157 EC2.179 J1.17 J1.77 J1.78 J1.A1 J1.A2 J1.A3 J1.A4 J1.A5 J1.A6 J1.A7 J1.A8 J2.A1 J2.A2 J2.A3 J2.A4 J2.A5 J2.A6 J2.A7 J2.A8 J3.A1 J3.A2 J3.A3 J3.A4 J3.A5 J3.A6 J3.A7 J3.A8 J4.2 J4.7 J5.1 J5.4 J5.9 J5.11 J5.13 J5.18 J5.23 J5.31 J5.32 J5.33 J5.34 J6.1 J6.5 J6.8 J6.15 J6.16 J6.17 J6.18 J6.21 J6.24 J6.31 J6.32 J6.33 J6.34 J6.41 J7.5 J8.4 J8.8 J9.1 J10.1 Q1.2 Q2.2 Q3.2 Q4.2 Q5.2 Q6.2 R2.2 R15.1 R16.1 R17.1 R18.1 R19.1 R20.1 R21.1 R22.1 R23.1 R58.2 R70.1 R71.1 R72.1 R73.1 R74.1 R75.1 R76.1 R77.1 R78.1 R81.2 R82.2 R83.2 R84.2 R89.2 R90.2 R93.2 R94.2 R97.2 R98.2 R106.2 R107.2 R114.2 R121.2 R129.2 R155.2 SW2.2 TP4.1 TP17.1 TP19.1 TP22.1 TP23.1 U1.49 U2.49 U3.3 U4.3 U5.3 U6.3 U7.3 U8.3 U9.3 U10.1 U10.11 U11.2 U12.2 U12.5 U13.3 U13.7@4597.11,-275.26 U14.2 U15.3@3548.54,2665.58 U15.8@3515.66,2665.58 U16.43 U17.43 U18.43 U19.5 U20.3 | length 8679.3
  Top Layer w8: v1(98.69,-357.47) U3.3@98.69,-327.53 ; v1(181.44,-203.82) 183.35,-205.73 200.23,-205.73 200.3,-205.79 U4.3@200.3,-208.54
  Top Layer w10: C32.2@0.38,-219.01 v1(0.38,-193.25) ; EC1.7@66.4,-528.32 66.4,-468.75 v1(82.15,-453) ; EC1.13@160.89,-528.32 163.1,-526.11 163.1,-468.31 v1(177.52,-453.88) ; EC1.19@255.38,-528.32 257.59,-526.11 257.59,-468.31 v1(270.59,-455.31) ; v1(287.22,-279.22) 287.22,-309.81 C33.2@287.45,-310.04 ; EC1.29@412.86,-528.32 v1(412.86,-453.88) ; C121.1@487.49,965.56 487.49,991.61 493.34,997.47 v1(518.75,997.47) ; EC1.35@507.34,-528.32 509.56,-526.11 509.56,-468.31 v1(523.98,-453.88) ; v1(681.02,-453.44) 695.88,-468.31 695.88,-527.88 EC1.47@696.32,-528.32 ; v1(763.44,393.12) 763.44,395.28 769.12,400.96 769.12,444.77 J1.78@769.23,444.88 ; v1(1095.77,-437.41) 1097.3,-438.94 1097.3,-442.81 1105.77,-451.28 v1(1105.77,-453.44) EC1.65@1105.77,-528.32 ; v1(1240,1661) R106.2@1264.16,1661 ; v1(1377,1482) 1358.9,1482 1353.04,1487.86 1353.04,1504.04 1361,1512 1401.5,1512 U19.5@1402.41,1512.91 ; EC1.83@1389.23,-528.32 1389.68,-527.88 1389.68,-468.31 v1(1404.1,-453.88) v1(1404.1,-427.85) ; v1(1530.22,1636.98) C118.2@1530.22,1664.99 ; EC1.97@1610.15,-527.88 1610.15,-468.31 v1(1624.57,-453.88) v1(1624.57,-427.85) ; R107.2@1690.35,1623.81 v1(1690.35,1651.65) ; EC1.111@1830.18,-528.32 1830.62,-527.88 1830.62,-468.31 v1(1845.04,-453.88) v1(1845.04,-427.85) ; v1(1890.51,2312.17) 1890.72,2311.96 1942.1,2311.96 U9.3@1942.3,2311.75 ; R97.2@2044.09,2691 v1(2072,2691) ; C71.1@2172.24,2386.55 v1(2172.24,2417) ; v1(2478,1540.9) 2478.33,1541.23 2517.02,1541.23 U8.3@2517.35,1541.57 ; v1(2497.52,1000.6) C18.2@2526.27,1000.6 ; v1(2497.52,1050.91) C7.2@2526.29,1050.93 ; v1(2497.52,1953.35) C54.2@2526.27,1953.35 ; v1(2497.52,2003.66) C43.2@2526.27,2003.66 ; Q2.2@2762.22,1456.91 v1(2800.09,1456.91) ; v1(2801.32,735) C20.2@2801.32,766.39 ; v3(2859,2434.07) U14.2@2899.89,2434.07 ; Q1.2@2909.66,1456.91 v1(2947.53,1456.91) ; v1(3034.87,951.91) 3034.87,969.72 3041.68,976.53 C12.2@3044.85,976.53 ; v1(3035.1,2076.06) 3035.16,2076 3047.14,2076 3053,2070.14 3053,2052.8 C50.2@3047.6,2047.4 ; v1@3035.23,1905 3035.23,1907.16 3040.01,1911.95 3040.01,1922.45 3046.82,1929.27 C48.2@3050.76,1929.27 ; v1(3035.79,1123.13) 3035.79,1101.45 3042.6,1094.64 C14.2@3044.85,1094.64 ; C3.2@3044.85,1035.59 v1(3073.75,1035.59) ; C39.2@3050.76,1988.11 v1(3079.66,1988.11) ; C105.1@3077.66,2518.72 v3(3077.66,2575.83) ; v1(3096,1531.71) Q3.2@3133.87,1531.71 ; R89.2@3107.87,2396.67 v1(3136.82,2396.67) ; C104.1@3133.66,2534.46 v3(3133.66,2575.83) ; v1(3276.81,2527.02) R93.2@3276.81,2559.81 ; R90.2@3276.81,2712.3 v1(3276.81,2745.09) ; v3(3301,2401) 3416.44,2401 3427.5,2412.06 C102.1@3427.5,2441.54 3427.5,2496.73 3434.31,2503.54 C103.2@3435.38,2503.54 ; EC2.157@3347.56,-522.97 3345.15,-520.56 3345.15,-455.81 v1(3362.42,-438.53) v1(3362.42,-412.5) ; v1(3525,2738) 3553.69,2738 3591.59,2700.1 3641.09,2700.1 J7.5@3641.15,2700.03 v1(3683,2700.03)
  Top Layer w12: v1(2672.24,2303.89) 2672.24,2251.76 2686.13,2237.87 C41.2@2722.6,2237.87 ; C5.2@2722.6,1285.11 2722.6,1289.05 2733.2,1299.65 v1(2762.75,1299.65) ; v1(2761.96,1720) 2762.81,1719.15 C56.2@2801.32,1719.15 ; v1(2791,2745.09) SW2.2@2791,2788 ; C73.1@2822.99,546.48 2853.75,546.48 2872.19,528.03 2872.19,516.69 v3(2874.49,514.4) ; C45.1@2945.8,1642.2 2945.8,1641.22 2958.5,1628.52 2959.48,1628.52 2971.29,1616.71 2989.52,1616.71 v1(2990.67,1615.56) ; C46.2@3009.3,1657.95 3009.3,1628.93 v1(3022.67,1615.56) ; U12.2@3197.74,484.88 v1(3197.74,512.04) ; v1(3449.47,192.19) C75.2@3483.41,192.19 ; v1(3488.2,2665.58) U15.8@3515.66,2665.58 U15.3@3548.54,2665.58 v1(3576,2665.58) ; C76.2@3611.5,328.4 3611.59,328.31 3611.59,305.88 v1(3611.68,305.79) ; v1(3671.05,-434.69) 3691.52,-455.16 3691.52,-520.47 EC2.179@3694.02,-522.97
  Top Layer w22: v3(1570.01,-215.3) C25.1@1570.01,-253 1576.62,-259.61 1576.62,-305.19 1577.43,-306 C26.2@1579.76,-306 ; v1(3290.4,294.41) v1(3290.4,265.41) C74.1@3341.94,265.41 3347.56,271.03 3377.37,271.03 3396.53,290.19 3427.48,290.19 U11.2@3428.29,291
  Top Layer w31.5: TP4.1@1827.22,-159.78 v3(1827.22,-193) C29.1@1827.22,-256.22 1827.22,-294.67 1840.76,-308.22 1842.96,-308.22 C30.2@1842.96,-312.16 ; C28.2@2003.41,-312.16 2003.41,-308.22 2005.54,-308.22 2019.16,-294.61 C27.1@2019.16,-256.16 v3(2019.16,-192.93) v3(2019.16,-159.78) v3(2019.16,-159.78)
  SIG1 w12: 3176.43,2586.43 v1(3212.89,2586.43) 3249.34,2586.43 ; 3176.43,2685.68 v1(3212.89,2685.68) 3249.35,2685.68
  Bottom w7.89: v1(229.05,938.68) J5.4@260.49,938.68
  Bottom w8: U5.3@373.84,-208.54 v1@390.92,-208.54 ; U6.3@599.81,-208.54 v1(619.71,-208.54)
  Bottom w9: J6.31@1199.93,2277.65 1225.43,2277.65 v1(1233.31,2285.52) 1225.43,2293.39 J6.33@1199.93,2293.39 ; J6.32@1306.63,2277.65 1281.13,2277.65 v1(1273.25,2285.52) 1281.13,2293.39 J6.34@1306.63,2293.39
  Bottom w9.05: v1(1276.25,2088.67) J6.8@1306.63,2088.67
  Bottom w10: v1(82.15,-453) 97.45,-468.31 97.45,-527.88 EC1.10@97.9,-528.32 ; C34.2@483.19,-309.7 483.19,-283.86 v1(503.43,-263.62) ; v1(523.98,-453.88) 538.4,-468.31 538.4,-527.88 EC1.38@538.84,-528.32 ; EC1.46@664.83,-528.32 666.15,-527 666.15,-468.31 v1(681.02,-453.44) ; v1(675.47,-339) C35.2@675.47,-309.7 ; U7.3@792.09,-208.54 792.35,-208.8 821.9,-208.8 v1(822.16,-209.07) ; C114.2@826.28,1231.26 827.02,1232 v1(859,1232) ; R155.2@907.02,-103 v1(948.07,-103) ; v1(950.4,832.69) C113.2@983.76,832.69 ; R83.2@1029.89,2324.89 v1(1029.89,2364.26) ; v1(1143.89,2364.26) 1145.88,2364.26 1153.75,2356.39 J6.41@1199.93,2356.39 ; J6.1@1199.93,2041.43 v1(1224.31,2041.43) ; v1(1238.04,1251.75) 1261.31,1251.75 C117.2@1262.94,1253.39 ; v1(1383.81,832.69) C115.2@1420.43,832.69 ; R81.2@1444.14,2217.4 1444.29,2217.56 1471.85,2217.56 v1(1472,2217.71) ; v1(1547.3,1247.37) 1571.89,1247.37 C116.2@1577.91,1253.39 ; v1(1867.17,868.98) 1867.53,869.33 1904.28,869.33 C110.2@1904.63,869.69 ; C111.2@1951.88,1231.89 1978.69,1231.89 1990.64,1219.94 v1(1992,1219.94) ; v1(2279.67,1058) 2279.67,1029.8 C109.2@2282.3,1027.17 ; v1(2352.42,2048.97) R70.1@2385.49,2048.97 ; v1(2352.42,2193.38) R71.1@2385.49,2193.38 ; v1(2481.36,835.44) R23.1@2514.42,835.44 ; v1(2481.36,2193.38) R77.1@2514.42,2193.38 ; v1(2481.36,2246.69) R78.1@2514.42,2246.69 ; R15.1@2501.95,1179.75 v1(2501.95,1211.5) ; R16.1@2501.95,1308.07 v1(2501.95,1351.13) ; R21.1@2501.95,1465.24 v1(2501.95,1497.38) ; R20.1@2672.24,1318.07 v1(2672.24,1351.13) ; R22.1@2672.24,1465.24 v1(2672.24,1497.38) ; R72.1@2672.24,2270.82 v1(2672.24,2303.89) ; v1(2800.09,1456.91) Q5.2@2838.99,1456.91 ; v1(2801.32,735) C19.2@2801.32,782.14 ; v1(2847.28,701.28) 2878.34,701.28 C2.2@2879.3,702.24 2883.91,697.63 2937.62,697.63 C1.1@2945.8,689.45 ; R19.1@2887.03,1318.07 v1(2887.03,1351.13) ; R74.1@2887.03,2270.82 v1(2887.03,2303.89) ; R75.1@2935.65,2270.82 v1(2935.65,2303.89) ; R18.1@2937.65,1318.07 v1(2937.65,1351.13) ; v1(2947.53,1456.91) Q4.2@2986.43,1456.91 ; v1(3034.87,951.91) 3034.98,952.02 3034.98,976.41 C11.2@3035.1,976.53 ; C8.2@3035.1,1035.59 v1(3073.75,1035.59) ; C13.2@3035.1,1094.64 3035.44,1094.99 3035.44,1122.79 v1(3035.79,1123.13) ; v1@3035.12,1904.9 C47.2@3035.1,1929.27 ; C44.2@3035.1,1988.11 v1(3079.66,1988.11) ; C49.2@3035.1,2047.4 3035.17,2047.46 v1@3035.17,2076 ; Q6.2@3057.1,1531.71 v1(3096,1531.71) ; v1(3059,1816) 3059,1843.08 R58.2@3059.11,1843.19 ; R17.1@3079.03,1318.07 v1(3079.03,1351.13) ; R73.1@3079.03,2270.82 v1(3079.03,2303.89) ; TP17.1@3236,2416 3265.77,2416 3275.78,2426 D1.1@3301.49,2426 ; v3(3301,2401) 3301.49,2401.49 D1.1@3301.49,2426 ; D1.1@3338.99,2475 3338.99,2463.5 D1.1@3301.49,2426 ; R114.2@3505.21,1088.92 3505.21,1082.42 3525.21,1062.42 3560.58,1062.42 v3(3563,1060) ; R121.2@3505.21,2017.19 3509.94,2012.47 R94.2@3585.95,2012.47 C120.1@3585.95,1927.86 ; C119.1@3588.57,982.92 3611,1005.35 v3(3611,1060) ; C120.1@3588.57,1910.14 3588.57,1927.86 3598.25,1937.55 3677.39,1937.55 3684.44,1944.6 3690,1939.04 v3(3690,1892)
  Bottom w12: C69.1@82.85,-55.76 C86.1@126.15,-55.76 C65.1@169.46,-55.76 C82.1@212.77,-55.76 ; v1(234.42,-23.76) 233.27,-24.9 219.8,-24.9 212.77,-31.93 C82.1@212.77,-55.76 ; v1(321.04,-23.76) 319.89,-24.9 306.41,-24.9 299.38,-31.93 C63.1@299.38,-55.76 ; v1(407.65,-23.76) 408.8,-24.9 422.27,-24.9 429.3,-31.93 C81.1@429.3,-55.76 ; v1(495.61,-23.76) 496.75,-24.9 508.89,-24.9 515.92,-31.93 C83.1@515.92,-55.76 ; v1(583.56,-23.76) 584.71,-24.9 596.84,-24.9 603.87,-31.93 C84.1@603.87,-55.76 ; v1(754.03,-21.55) 752.88,-22.7 750.72,-22.7 739.41,-34.01 739.41,-50.14 C68.1@733.8,-55.76 ; v1(841.91,-22.15) 841.43,-21.66 827.44,-21.66 820.41,-28.69 C70.1@820.41,-55.76 ; C94.1@863.72,-55.76 C70.1@820.41,-55.76 ; R82.2@1029.89,2423.63 R82.2@1029.89,2423.63 1029.95,2449.95 v1(1030,2450) ; v1(1117.43,1258.39) 1118.58,1257.24 1137.39,1257.24 C112.2@1141.24,1253.39 ; v3(1373.17,2475) 1373.17,2473.38 1384.7,2461.85 1384.7,2435.38 C60.2@1384.45,2435.13 ; v3(1411,2475) 1412.34,2473.66 1428.09,2473.66 1435.12,2466.63 1435.12,2463.58 C59.1@1447.82,2450.88 ; C61.1@1523.47,2563.73 1509,2578.2 v3(1509,2651) 1509,2674.69 1516.03,2681.72 1565.19,2681.72 R84.2@1566.2,2682.73 ; v1(2482.69,1788.19) R76.1@2514.42,1788.19 ; v3(2837,1655) C38.2@2879.3,1655 2933.1,1655 2945.8,1642.3 C31.1@2945.8,1642.2 2945.8,1641.22 2958.5,1628.52 2959.48,1628.52 2971.29,1616.71 2989.52,1616.71 v1(2990.67,1615.56) ; v1(2860.67,443.17) 2862.29,443.17 2868.36,437.1 C77.2@2911.03,437.1 ; C82.1@212.77,-55.76 C80.1@256.07,-55.76 C63.1@299.38,-55.76 ; C63.1@299.38,-55.76 C79.1@342.69,-55.76 C62.1@386,-55.76 C81.1@429.3,-55.76 ; C81.1@429.3,-55.76 C64.1@472.61,-55.76 C83.1@515.92,-55.76 ; C83.1@515.92,-55.76 C66.1@559.22,-55.76 C84.1@603.87,-55.76 ; C84.1@603.87,-55.76 C67.1@647.18,-55.76 C85.1@690.49,-55.76 C68.1@733.8,-55.76 ; C68.1@733.8,-55.76 C87.1@777.1,-55.76 C70.1@820.41,-55.76
  Bottom w22: C58.2@1384.45,1992.98 1384.45,1989.04 1385.26,1988.23 1389.2,1988.23 1400.2,1977.23 C57.1@1441.93,1977.23 1446.01,1981.31 v1(1489.11,1981.31)
  other v1: 125.25,-269.41 390.92,-208.92 3246.36,399.27 3218,427.64 3177.86,471.89 2990.67,664.91 3024.32,664.91 2615.13,697.15 2703.84,696.46 2742.55,696.46 1858,834 90,1101 167.24,1156 232.48,1156 -113.34,1412.55 -113.34,1494.14 2703.84,1642.22 2742.55,1642.22 2665.13,1642.9 3035.1,1904.88 1233.31,2161.39 1273.25,2161.39 1105.89,2165.97 1233.31,2191.03 1273.25,2191.03 2701.39,2269.39 10.49,2331.19 148,2331.19
  other v2: 4597.11,-296.91 4597.11,-253.6 2114.98,888.98 2084.47,935.04 2114.98,935.04 2145.49,935.04 2764.52,954.89 2818.46,954.89 2084.47,981.1 2114.98,981.1 2145.49,981.1 2720.62,998.78 2764.52,998.78 2818.46,998.78 2862.35,998.78 891.64,1012.53 937.7,1012.53 983.76,1012.53 1029.82,1012.53 1075.89,1012.53 1328.3,1012.53 1374.36,1012.53 1420.43,1012.53 1466.49,1012.53 1512.55,1012.53 2084.47,1027.17 2114.98,1027.17 2145.49,1027.17 845.57,1043.04 891.64,1043.04 937.7,1043.04 983.76,1043.04 1029.82,1043.04 1075.89,1043.04 1121.95,1043.04 1282.24,1043.04 1328.3,1043.04 1374.36,1043.04 1420.43,1043.04 1466.49,1043.04 1512.55,1043.04 1558.61,1043.04 2720.62,1052.72 2764.52,1052.72 2818.46,1052.72 2862.35,1052.72 2084.47,1073.23 2114.98,1073.23 2145.49,1073.23 891.64,1073.55 937.7,1073.55 983.76,1073.55 1029.82,1073.55 1075.89,1073.55 1328.3,1073.55 1374.36,1073.55 1420.43,1073.55 1466.49,1073.55 1512.55,1073.55 2764.52,1096.62 2818.46,1096.62 2084.47,1119.29 2114.98,1119.29 2145.49,1119.29 2114.98,1165.35 2764.52,1907.64 2818.46,1907.64 2720.62,1951.54 2764.52,1951.54 2818.46,1951.54 2862.35,1951.54 2720.62,2005.48 2764.52,2005.48 2818.46,2005.48 2862.35,2005.48 2764.52,2049.37 2818.46,2049.37
  other v3: 2838.49,493.74 3642,1844 3690,1844 3642,1892 1475.14,2651
GPIO_2/CLKOUT: J6.48
HDR_DAC_TCK: J4.4 R158.1 | length 3417.9
  Top Layer w5.66: J4.4@966.91,2620.91 919.66,2573.67 919.66,2572.76 864,2517.1 864,1560 376.34,1072.34 376.34,1044.66 388.83,1032.17 638.83,1032.17 795,876 795,719 991.81,522.19 1126.29,522.19 1265.66,661.57 1562.58,661.57 1570.71,653.44 R158.1@1570.71,620.28
HDR_DAC_TDI: J4.5 R156.1 | length 3681.4
  Top Layer w5.66: v1(1441.67,44.29) 1442.43,44.29 1453.26,33.46 R156.1@1478.63,33.46
  Bottom w5.66: J4.5@866.91,2720.91 826.17,2680.18 826.17,2242.68 929.02,2139.83 929.02,1628.83 616.36,1316.17 616.36,966.02 783.28,799.1 783.28,338.54 773.63,328.89 773.63,262.12 829.15,206.6 1115.3,206.6 1195.33,286.63 1301.15,286.63 1317.13,270.65 1346.44,270.65 1357.37,259.72 1357.37,98.4 1411.48,44.29 v1(1441.67,44.29)
HDR_DAC_TDO: J4.6 R157.1 | length 3572.7
  Top Layer w5.66: v1(1442.6,72.32) 1445.94,72.32 1451.89,78.27 1478.07,78.27 R157.1@1478.63,78.82
  Bottom w5.66: J4.6@866.91,2620.91 866.91,2219.84 941.68,2145.07 941.68,1623.53 629.02,1310.87 629.02,971.26 795.94,804.34 795.94,330.75 788.25,323.06 788.25,279.29 796.7,270.84 818.41,270.84 828.03,261.23 828.03,233.1 841.87,219.26 1110.05,219.26 1218.23,327.44 1349.12,327.44 1370.03,306.54 1370.03,112.98 1410.69,72.32 v1(1442.6,72.32)
HDR_DAC_TMS: J4.3 R161.1 | length 3436.8
  Top Layer w5.66: J4.3@966.91,2720.91 918,2672.01 918,2589.91 907,2578.91 907,2578 849,2520 849,1562.9 363.68,1077.59 363.68,1039.41 383.59,1019.51 612.76,1019.51 782.34,849.92 782.34,713.76 953.1,543 986.57,509.53 1131.53,509.53 1242.28,620.28 R161.1@1524.04,620.28
HDR_FSIRX0_CLK: J8.3 R39.1 | length 3889.7
  Top Layer w5.66: v1(1332.54,0.86) R39.1@1332.54,33.25
  Bottom w5.66: J8.3@12.26,2711 362.94,2360.32 466.71,2360.32 802.42,2024.61 802.42,1645.46 515.08,1358.12 515.08,1141.82 462.94,1089.68 462.94,568.09 613.61,417.42 613.61,278.91 787.2,105.32 1228.07,105.32 v1(1332.54,0.86)
HDR_FSIRX0_DATA0: J8.1 R126.1 | length 4016.5
  Top Layer w5.66: v1(1143.31,0.86) R126.1@1143.31,33.25
  Bottom w5.66: J8.1@-66.48,2711 -66.48,2629.75 -56.37,2619.63 -50.9,2614.17 -43.64,2614.17 -13.89,2643.92 -6.64,2643.92 4.25,2633.03 4.25,2625.77 -27.07,2594.46 -27.07,2587.2 -16.18,2576.31 -8.92,2576.31 22.39,2607.63 29.65,2607.63 40.54,2596.74 40.54,2589.48 10.79,2559.74 10.79,2552.48 30.94,2532.33 228.27,2335 456.22,2335 745.96,2045.26 745.96,1934.74 777.1,1903.6 777.1,1655.95 489.76,1368.61 489.76,1152.31 437.62,1100.17 437.62,557.6 588.29,406.93 588.29,268.43 776.71,80 1064.16,80 v1(1143.31,0.86)
HDR_FSIRX0_DATA1: J8.2 R41.1 | length 3960
  Top Layer w5.66: R41.1@1237.92,33.25 1238.99,32.18 v1(1238.99,1.93)
  Bottom w5.66: J8.2@-66.48,2789.74 -24.93,2748.19 -24.93,2682.26 74.66,2582.66 74.66,2557.09 99.57,2532.19 125.14,2532.19 309.67,2347.66 461.46,2347.66 758.62,2050.5 758.62,1939.98 789.76,1908.85 789.76,1650.71 502.42,1363.37 502.42,1147.06 450.28,1094.92 450.28,562.84 600.95,412.17 600.95,273.67 781.96,92.66 1148.26,92.66 v1(1238.99,1.93)
HSEC_ADC0_AIN0/DAC_OUT: C79.2 EC1.9 R134.2 U3.1 | length 816.2
  Top Layer w5.66: v1(14,-306.12) 51.37,-306.12 59.32,-314.06 U3.1@59.32,-327.53 59.32,-378.32 107.31,-426.31 107.31,-460.96 97.9,-470.38 EC1.9@97.9,-528.32 ; R134.2@342.69,-103 342.69,-127.24 346,-130.55 358.78,-130.55 v1(359.98,-131.75)
  SIG1 w6.66: v1(14,-306.12) 227.54,-306.12 359.98,-173.68 v1(359.98,-131.75)
  Bottom w5.66: C79.2@342.69,-103 342.69,-127.24 346,-130.55 358.78,-130.55 v1(359.98,-131.75)
HSEC_ADC0_AIN1: C62.2 EC1.11 R135.2 U3.2 | length 885.9
  Top Layer w5.66: v1(14,-272) 35,-293 56.16,-293 77.95,-314.8 77.95,-326.48 U3.2@79,-327.53 79,-376 119.97,-416.97 119.97,-460.96 129.39,-470.38 EC1.11@129.39,-528.32 ; v1(386,-131.75) R135.2@386,-103
  SIG1 w6.66: v1(14,-272) 79.53,-272 98.53,-291 223.34,-291 335.52,-178.82 335.52,-115.42 341.75,-109.19 380.95,-109.19 385.86,-114.1 385.86,-131.62 v1(386,-131.75)
  Bottom w5.66: v1(386,-131.75) C62.2@386,-103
